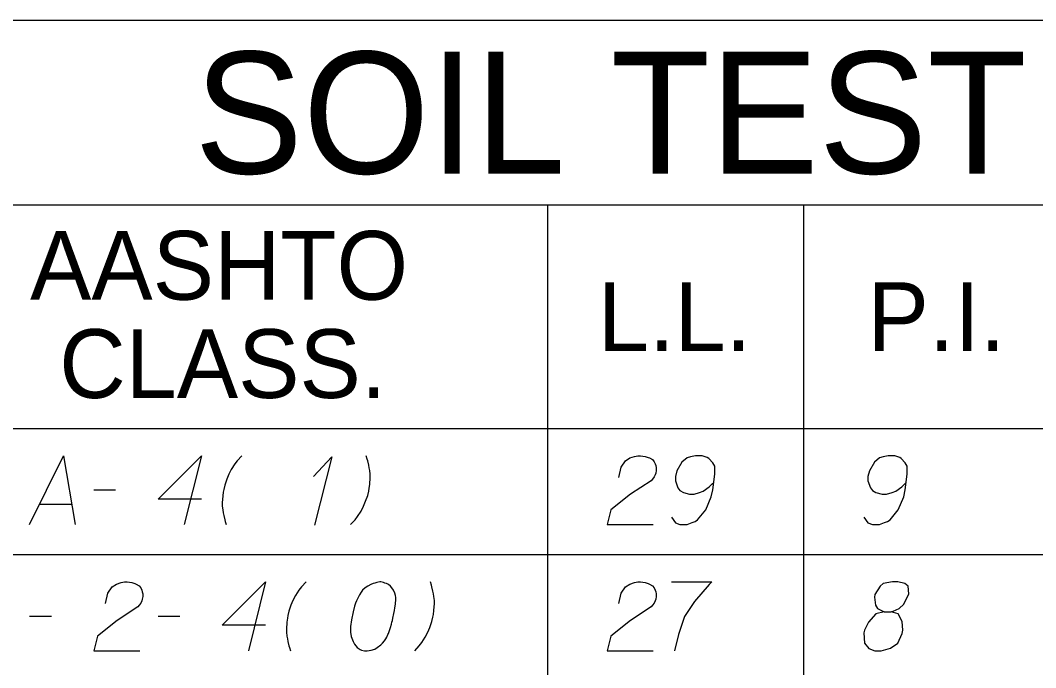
# Model space of a CAD drawing. Extents: x 2074207 to 2076812, y 516372 to 523312.
# Drawn here: x 2076453.5 to 2076524.4, y 518123.4 to 518168.6 of the extents above; entities that cross this region are included whole.
import ezdxf

# ---------------------------------------------------------------- set-up
doc = ezdxf.new("R2010")
doc.units = 0
for name, color, linetype in [('Prop DirtTable_ Soil Test Results - Outline (Major)', 7, 'Continuous'), ('Prop DirtTable_ Soil Test Results - Outline (Minor)', 7, 'Continuous'), ('Prop DirtTable_ Soil Test Results - Tx (Header - Large)', 7, 'Continuous'), ('Prop DirtTable_ Soil Test Results - Tx (Header - Small)', 7, 'Continuous'), ('Prop DirtTable_ Soil Test Results - Tx (Sample Data)', 7, 'Continuous')]:
    doc.layers.add(name, color=color, linetype=linetype)

msp = doc.modelspace()

# ---------------------------------------------------------------- linework, layer by layer
at = {"layer": 'Prop DirtTable_ Soil Test Results - Outline (Major)'}
for p, q in [((2076260.609, 518168.566), (2076811.903, 518168.566)), ((2076260.609, 518140.08), (2076811.903, 518140.08)), ((2076260.609, 518140.08), (2076811.903, 518140.08))]:
    msp.add_line(p, q, dxfattribs=at)
at = {"layer": 'Prop DirtTable_ Soil Test Results - Outline (Minor)'}
for p, q in [((2076260.609, 518155.68), (2076811.903, 518155.68)), ((2076490.31, 518155.68), (2076490.31, 518131.28)), ((2076508.192, 518155.68), (2076508.192, 518131.28)), ((2076260.609, 518131.28), (2076811.903, 518131.28)), ((2076260.609, 518131.28), (2076811.903, 518131.28)), ((2076490.31, 518131.28), (2076490.31, 518122.48)), ((2076508.192, 518131.28), (2076508.192, 518122.48))]:
    msp.add_line(p, q, dxfattribs=at)
at = {"layer": 'Prop DirtTable_ Soil Test Results - Tx (Sample Data)'}
for points in [[(2076454.156, 518133.375), (2076456.519, 518138.175), (2076457.33, 518133.375)], [(2076466.149, 518135.152), (2076463.116, 518135.152), (2076466.149, 518138.175), (2076464.95, 518133.375)], [(2076468.971, 518138.175), (2076468.654, 518137.835), (2076468.478, 518137.608), (2076468.231, 518137.23), (2076468.054, 518136.89), (2076467.913, 518136.55), (2076467.772, 518136.134), (2076467.701, 518135.832), (2076467.666, 518135.643), (2076467.631, 518135.378), (2076467.596, 518134.887), (2076467.596, 518134.66), (2076467.631, 518134.396), (2076467.666, 518134.207), (2076467.701, 518134.018), (2076467.772, 518133.715), (2076467.807, 518133.602), (2076467.878, 518133.375)], [(2076476.556, 518133.375), (2076476.873, 518133.715), (2076477.049, 518133.942), (2076477.296, 518134.32), (2076477.473, 518134.66), (2076477.614, 518135), (2076477.755, 518135.416), (2076477.826, 518135.718), (2076477.861, 518135.907), (2076477.896, 518136.172), (2076477.931, 518136.663), (2076477.931, 518136.89), (2076477.896, 518137.155), (2076477.861, 518137.344), (2076477.826, 518137.533), (2076477.755, 518137.835), (2076477.72, 518137.948), (2076477.649, 518138.175)], [(2076495.287, 518136.663), (2076495.463, 518137.381), (2076495.746, 518137.835), (2076496.063, 518138.024), (2076496.38, 518138.137), (2076496.627, 518138.175), (2076496.804, 518138.175), (2076497.121, 518138.137), (2076497.333, 518138.062), (2076497.439, 518138.024), (2076497.65, 518137.911), (2076497.756, 518137.759), (2076497.827, 518137.608), (2076497.862, 518137.495), (2076497.897, 518137.344), (2076497.897, 518137.155), (2076497.862, 518136.966), (2076497.827, 518136.852), (2076497.756, 518136.701), (2076497.65, 518136.55), (2076497.545, 518136.437), (2076496.098, 518135.492), (2076494.723, 518134.396), (2076494.476, 518133.375), (2076497.686, 518133.375)], [(2076498.956, 518133.904), (2076499.238, 518133.489), (2076499.555, 518133.375), (2076500.049, 518133.375), (2076500.402, 518133.526), (2076500.614, 518133.602), (2076500.79, 518133.715), (2076501.354, 518134.396), (2076501.742, 518135.303), (2076501.848, 518135.794), (2076501.989, 518136.89), (2076501.989, 518137.457), (2076501.848, 518137.684), (2076501.566, 518137.986), (2076501.46, 518138.062), (2076501.107, 518138.175), (2076500.649, 518138.175), (2076500.296, 518138.1), (2076500.049, 518138.024), (2076499.696, 518137.722), (2076499.344, 518137.117), (2076499.238, 518136.739), (2076499.238, 518136.437), (2076499.414, 518135.945), (2076499.555, 518135.756), (2076499.802, 518135.605), (2076500.226, 518135.492), (2076500.543, 518135.492), (2076500.931, 518135.605), (2076501.178, 518135.718), (2076501.601, 518136.021), (2076501.813, 518136.21), (2076501.919, 518136.323)], [(2076512.396, 518133.904), (2076512.678, 518133.489), (2076512.995, 518133.375), (2076513.489, 518133.375), (2076513.842, 518133.526), (2076514.054, 518133.602), (2076514.23, 518133.715), (2076514.794, 518134.396), (2076515.182, 518135.303), (2076515.288, 518135.794), (2076515.429, 518136.89), (2076515.429, 518137.457), (2076515.288, 518137.684), (2076515.006, 518137.986), (2076514.9, 518138.062), (2076514.547, 518138.175), (2076514.089, 518138.175), (2076513.736, 518138.1), (2076513.489, 518138.024), (2076513.136, 518137.722), (2076512.784, 518137.117), (2076512.678, 518136.739), (2076512.678, 518136.437), (2076512.854, 518135.945), (2076512.995, 518135.756), (2076513.242, 518135.605), (2076513.666, 518135.492), (2076513.983, 518135.492), (2076514.371, 518135.605), (2076514.618, 518135.718), (2076515.041, 518136.021), (2076515.253, 518136.21), (2076515.359, 518136.323)], [(2076473.98, 518136.739), (2076475.25, 518138.1), (2076474.051, 518133.337)], [(2076458.636, 518135.794), (2076460.152, 518135.794)], [(2076454.861, 518134.811), (2076457.083, 518134.811)], [(2076459.447, 518127.863), (2076459.623, 518128.581), (2076459.906, 518129.035), (2076460.223, 518129.224), (2076460.54, 518129.337), (2076460.787, 518129.375), (2076460.964, 518129.375), (2076461.281, 518129.337), (2076461.493, 518129.262), (2076461.599, 518129.224), (2076461.81, 518129.111), (2076461.916, 518128.959), (2076461.987, 518128.808), (2076462.022, 518128.695), (2076462.057, 518128.544), (2076462.057, 518128.355), (2076462.022, 518128.166), (2076461.987, 518128.052), (2076461.916, 518127.901), (2076461.81, 518127.75), (2076461.705, 518127.637), (2076460.258, 518126.692), (2076458.883, 518125.596), (2076458.636, 518124.575), (2076461.846, 518124.575)], [(2076470.629, 518126.352), (2076467.596, 518126.352), (2076470.629, 518129.375), (2076469.43, 518124.575)], [(2076473.451, 518129.375), (2076473.134, 518129.035), (2076472.958, 518128.808), (2076472.711, 518128.43), (2076472.534, 518128.09), (2076472.393, 518127.75), (2076472.252, 518127.334), (2076472.181, 518127.032), (2076472.146, 518126.843), (2076472.111, 518126.578), (2076472.076, 518126.087), (2076472.076, 518125.86), (2076472.111, 518125.596), (2076472.146, 518125.407), (2076472.181, 518125.218), (2076472.252, 518124.915), (2076472.287, 518124.802), (2076472.358, 518124.575)], [(2076478.672, 518129.375), (2076478.602, 518129.375), (2076478.39, 518129.337), (2076478.249, 518129.3), (2076478.143, 518129.262), (2076477.967, 518129.186), (2076477.755, 518129.073), (2076477.579, 518128.959), (2076477.402, 518128.808), (2076477.296, 518128.657), (2076477.191, 518128.468), (2076477.085, 518128.279), (2076476.979, 518128.052), (2076476.908, 518127.901), (2076476.838, 518127.674), (2076476.732, 518127.296), (2076476.626, 518126.729), (2076476.556, 518126.276), (2076476.556, 518125.86), (2076476.591, 518125.558), (2076476.732, 518125.218), (2076476.838, 518125.029), (2076477.014, 518124.802), (2076477.226, 518124.651), (2076477.332, 518124.613), (2076477.543, 518124.575), (2076477.72, 518124.575), (2076478.002, 518124.613), (2076478.249, 518124.689), (2076478.425, 518124.802), (2076478.672, 518124.991), (2076478.778, 518125.104), (2076478.919, 518125.255), (2076479.025, 518125.407), (2076479.095, 518125.52), (2076479.166, 518125.709), (2076479.201, 518125.785), (2076479.272, 518125.974), (2076479.342, 518126.2), (2076479.413, 518126.427), (2076479.448, 518126.578), (2076479.483, 518126.692), (2076479.519, 518126.843), (2076479.589, 518127.183), (2076479.625, 518127.372), (2076479.66, 518127.561), (2076479.695, 518127.826), (2076479.73, 518128.166), (2076479.73, 518128.279), (2076479.695, 518128.43), (2076479.66, 518128.581), (2076479.554, 518128.808), (2076479.448, 518128.959), (2076479.342, 518129.073), (2076479.201, 518129.186), (2076479.06, 518129.262), (2076478.954, 518129.3), (2076478.849, 518129.337), (2076478.672, 518129.375)], [(2076481.036, 518124.575), (2076481.353, 518124.915), (2076481.529, 518125.142), (2076481.776, 518125.52), (2076481.953, 518125.86), (2076482.094, 518126.2), (2076482.235, 518126.616), (2076482.306, 518126.918), (2076482.341, 518127.107), (2076482.376, 518127.372), (2076482.411, 518127.863), (2076482.411, 518128.09), (2076482.376, 518128.355), (2076482.341, 518128.544), (2076482.306, 518128.733), (2076482.235, 518129.035), (2076482.2, 518129.148), (2076482.129, 518129.375)], [(2076495.287, 518127.863), (2076495.463, 518128.581), (2076495.746, 518129.035), (2076496.063, 518129.224), (2076496.38, 518129.337), (2076496.627, 518129.375), (2076496.804, 518129.375), (2076497.121, 518129.337), (2076497.333, 518129.262), (2076497.439, 518129.224), (2076497.65, 518129.111), (2076497.756, 518128.959), (2076497.827, 518128.808), (2076497.862, 518128.695), (2076497.897, 518128.544), (2076497.897, 518128.355), (2076497.862, 518128.166), (2076497.827, 518128.052), (2076497.756, 518127.901), (2076497.65, 518127.75), (2076497.545, 518127.637), (2076496.098, 518126.692), (2076494.723, 518125.596), (2076494.476, 518124.575), (2076497.686, 518124.575)], [(2076498.956, 518129.375), (2076501.778, 518129.375), (2076501.601, 518129.186), (2076500.578, 518128.015), (2076499.873, 518126.956), (2076499.449, 518125.709), (2076499.167, 518124.575)], [(2076513.807, 518127.296), (2076514.3, 518127.296), (2076514.442, 518127.334), (2076514.865, 518127.523), (2076515.182, 518127.826), (2076515.535, 518128.544), (2076515.5, 518129.073), (2076515.253, 518129.262), (2076514.759, 518129.375), (2076514.406, 518129.375), (2076513.736, 518129.262), (2076513.524, 518129.073), (2076513.172, 518128.506), (2076513.136, 518128.317), (2076513.207, 518127.75), (2076513.348, 518127.523), (2076513.807, 518127.296), (2076513.242, 518127.145), (2076512.713, 518126.578), (2076512.431, 518126.011), (2076512.396, 518125.822), (2076512.431, 518125.104), (2076512.748, 518124.726), (2076513.172, 518124.575), (2076513.595, 518124.575), (2076514.265, 518124.764), (2076514.759, 518125.104), (2076515.077, 518125.785), (2076515.112, 518126.011), (2076515.077, 518126.616), (2076514.794, 518127.145), (2076514.3, 518127.296)], [(2076454.156, 518126.994), (2076455.672, 518126.994)], [(2076463.116, 518126.994), (2076464.632, 518126.994)]]:
    msp.add_lwpolyline(points, dxfattribs=at)

# ---------------------------------------------------------------- texts
at = {"layer": 'Prop DirtTable_ Soil Test Results - Tx (Header - Large)'}
msp.add_text('SOIL TEST RESULTS', height=8.50001, dxfattribs=at).set_placement((2076465.656, 518157.873))
at = {"layer": 'Prop DirtTable_ Soil Test Results - Tx (Header - Small)'}
for s, p in [('AASHTO', (2076454.182, 518149.067)), ('L.L.', (2076493.827, 518145.48)), ('P.I.', (2076512.654, 518145.48)), ('CLASS.', (2076456.225, 518142.21))]:
    msp.add_text(s, height=4.8, dxfattribs=at).set_placement(p)

doc.saveas('drawing.dxf')
